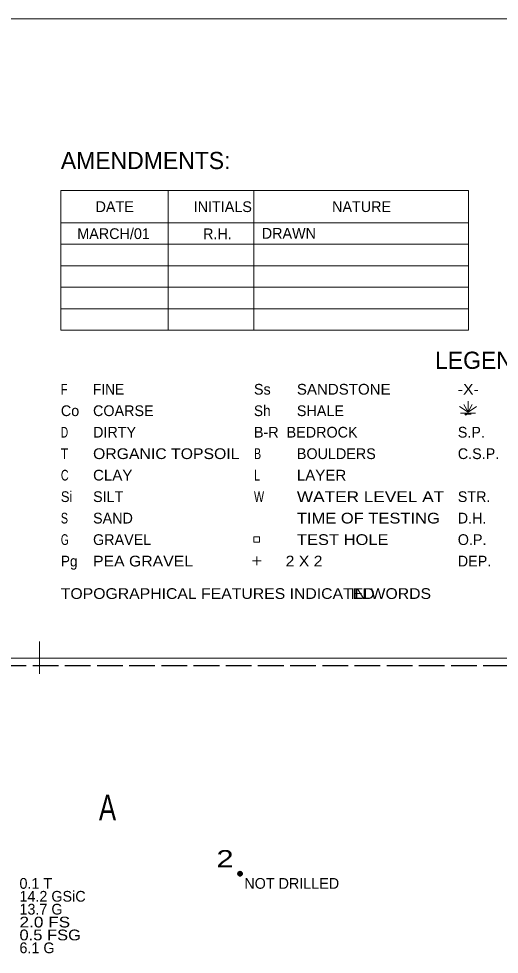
# Model space of a CAD drawing. Extents: x -496 to 480, y -450 to 700.
# Drawn here: x -9.7 to 214.3, y 264.4 to 700 of the extents above; entities that cross this region are included whole.
import ezdxf
from ezdxf.enums import TextEntityAlignment as Align

# ---------------------------------------------------------------- set-up
doc = ezdxf.new("R2010")
doc.units = 0
doc.header["$LTSCALE"] = 2
doc.header["$PDMODE"] = 32
doc.header["$PDSIZE"] = 1
doc.linetypes.add('LONG_DASHED', pattern=[7.5, 6, -1.5])
doc.layers.add('1', color=7, linetype='Continuous', lineweight=13)
doc.layers.add('2', color=7, linetype='Continuous', lineweight=35)

msp = doc.modelspace()

# ---------------------------------------------------------------- linework, layer by layer
at = {"layer": '1'}
for p, q in [((199.983, 619.973), (9.983, 619.973)), ((9.983, 619.973), (9.983, 554.973)), ((59.983, 619.973), (59.983, 554.973)), ((99.983, 619.973), (99.983, 554.973)), ((199.983, 554.973), (199.983, 619.973)), ((9.983, 604.973), (199.983, 604.973)), ((9.983, 594.973), (199.983, 594.973)), ((9.983, 584.973), (199.983, 584.973)), ((9.983, 574.973), (199.983, 574.973)), ((9.983, 564.973), (199.983, 564.973)), ((199.76, 516.875), (195.76, 519.375)), ((199.76, 516.875), (197.76, 520.375)), ((199.76, 516.875), (199.76, 521.875)), ((199.76, 516.875), (201.76, 520.375)), ((199.76, 516.875), (203.76, 519.375)), ((196.26, 516.375), (203.26, 516.375)), ((198.26, 515.875), (201.26, 515.875)), ((101.291, 449.597), (101.291, 445.597)), ((103.353, 447.618), (99.353, 447.618)), ((-0.017, 394.973), (-0.017, 409.973))]:
    msp.add_line(p, q, dxfattribs=at)
for points in [[(449.983, -450.027), (449.983, 399.973), (449.983, 699.973), (-450.017, 699.973), (-450.017, 49.973), (-450.017, -450.027)], [(9.983, 554.973), (99.983, 554.973), (199.983, 554.973)], [(402.281, -402.333), (402.281, 402.339), (-402.391, 402.339)]]:
    msp.add_lwpolyline(points, dxfattribs=at)
msp.add_lwpolyline([(99.967, 456.301), (99.967, 458.832), (102.499, 458.832), (102.499, 456.301)], close=True, dxfattribs=at)
msp.add_point((198.76, 515.875), dxfattribs=at)
at = {"layer": '2', "linetype": 'LONG_DASHED', "lineweight": 25}
msp.add_line((398.852, 398.739), (-292.391, 398.739), dxfattribs=at)
at = {"layer": '2'}
msp.add_circle((93.501, 301.926), 1, dxfattribs=at)
msp.add_spline([(93.49, 302.813), (94.22, 302.409), (94.372, 301.56), (93.687, 301.032), (92.878, 301.263), (92.591, 302.021), (92.838, 302.583), (93.411, 302.751), (94.085, 302.257), (94.069, 301.515), (93.552, 301.257), (93.029, 301.426), (92.805, 302.072), (93.389, 302.538), (93.827, 302.004), (93.788, 301.521), (93.159, 301.656), (93.305, 302.291), (93.597, 301.74)], degree=3, dxfattribs=at)

# ---------------------------------------------------------------- texts
at = {"layer": '1'}
for s, height, p in [('AMENDMENTS:', 8, (9.983, 629.973)), ('Ss', 5, (99.983, 524.973)), ('Co', 5, (9.983, 514.973)), ('COARSE', 5, (24.983, 514.973)), ('SHALE', 5, (119.983, 514.973)), ('DIRTY', 5, (24.983, 504.973)), ('B-R  BEDROCK', 5, (99.983, 504.973)), ('S.P.', 5, (194.983, 504.973)), ('BOULDERS', 5, (119.983, 494.973)), ('C.S.P.', 5, (194.983, 494.973)), ('SILT', 5, (24.983, 474.973)), ('STR.', 5, (194.983, 474.973)), ('SAND', 5, (24.983, 464.973)), ('D.H.', 5, (194.983, 464.973)), ('GRAVEL', 5, (24.983, 454.973)), ('O.P.', 5, (194.983, 454.973)), ('DEP.', 5, (194.983, 444.973))]:
    msp.add_text(s, height=height, dxfattribs=at).set_placement(p)
for s, height, p in [('DATE', 5, (35.081, 609.973)), ('INITIALS', 5, (85.453, 609.973)), ('NATURE', 5, (150.16, 609.973)), ('MARCH/01', 5, (34.552, 597.405)), ('R.H.', 5, (82.941, 597.343)), ('DRAWN', 5, (116.266, 597.567)), ('LEGEND', 8, (206.378, 536.973))]:
    msp.add_text(s, height=height, dxfattribs=at).set_placement(p, align=Align.CENTER)
for s, width, p in [('F', 0.75, (9.983, 524.973)), ('FINE', 0.95, (24.983, 524.973)), ('SANDSTONE', 1.05, (119.983, 524.973)), ('-X-', 1.1, (194.983, 524.973)), ('Sh', 0.95, (99.983, 514.973)), ('D', 0.7, (9.983, 504.973)), ('T', 0.85, (9.983, 494.973)), ('ORGANIC TOPSOIL', 1.1, (24.983, 494.973)), ('B', 0.75, (99.983, 494.973)), ('C', 0.75, (9.983, 484.973)), ('CLAY', 1.05, (24.983, 484.973)), ('L', 0.75, (99.983, 484.973)), ('LAYER', 1.05, (119.983, 484.973)), ('Si', 0.9, (9.983, 474.973)), ('W', 0.75, (99.983, 474.973)), ('WATER LEVEL AT', 1.2, (119.983, 474.973)), ('S', 0.75, (9.983, 464.973)), ('TIME OF TESTING', 1.15, (119.983, 464.973)), ('G', 0.7, (9.983, 454.973)), ('TEST HOLE', 1.15, (119.983, 454.973)), ('Pg', 0.95, (9.983, 444.973)), ('PEA GRAVEL', 1.1, (24.983, 444.973)), ('   2 X 2', 1.1, (108.608, 444.973)), ('TOPOGRAPHICAL FEATURES INDICATED', 1.1, (9.942, 429.855)), ('IN WORDS', 1.1, (144.942, 429.855))]:
    msp.add_text(s, height=5, dxfattribs=dict(at, width=width)).set_placement(p)
at = {"layer": '2', "width": 0.75}
msp.add_text('A', height=12, dxfattribs=at).set_placement((31.728, 326.734), align=Align.CENTER)
at = {"layer": '2', "width": 1.35}
msp.add_text('  2', height=8, dxfattribs=at).set_placement((90.5, 304.926), align=Align.RIGHT)
at = {"layer": '2'}
for s, p in [('0.1 T      ', (-9.304, 294.926)), ('NOT DRILLED', (95.501, 294.926)), ('14.2 GSiC  ', (-9.304, 288.926)), ('13.7 G     ', (-9.304, 282.926)), ('6.1 G      ', (-9.304, 264.926))]:
    msp.add_text(s, height=5, dxfattribs=at).set_placement(p)
for s, width, p in [('2.0 FS     ', 1.2, (-9.304, 276.926)), ('0.5 FSG    ', 1.15, (-9.304, 270.926))]:
    msp.add_text(s, height=5, dxfattribs=dict(at, width=width)).set_placement(p)

doc.saveas('drawing.dxf')
